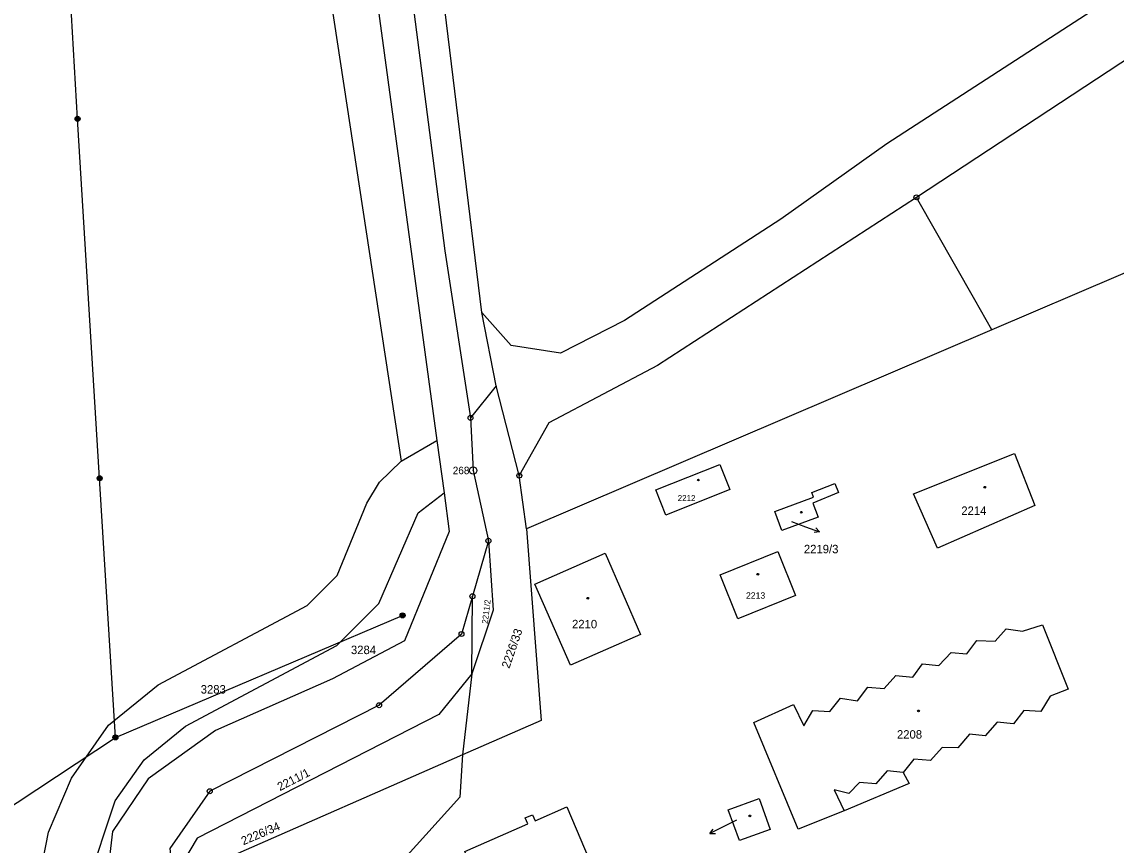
# Model space of a CAD drawing. Extents: x -504988 to -494607, y -1123820 to -1114018.
# Drawn here: x -498417.5 to -498197.3, y -1121313.5 to -1121148 of the extents above; entities that cross this region are included whole.
import ezdxf

# ---------------------------------------------------------------- set-up
doc = ezdxf.new("R2010")
doc.units = 0
for name, color, linetype in [('Hranice parcel', 7, 'Continuous'), ('Parcelní čísla', 7, 'Continuous'), ('Pop  PČ popisy', 7, 'Continuous'), ('Poz předměty', 7, 'Continuous'), ('Vnitřní kresba', 7, 'Continuous'), ('Značky bodu BP', 7, 'Continuous'), ('Značky budov', 7, 'Continuous')]:
    doc.layers.add(name, color=color, linetype=linetype)

msp = doc.modelspace()

# ---------------------------------------------------------------- linework, layer by layer
at = {"layer": 'Hranice parcel'}
for p, q in [((-498322.08, -1121221.18), (-498324.96, -1121206.38)), ((-498322.08, -1121221.18), (-498327.26, -1121227.59)), ((-498317.44, -1121239.21), (-498322.08, -1121221.18)), ((-498341.22, -1121236.34), (-498334.01, -1121232.13)), ((-498334.01, -1121232.13), (-498332.57, -1121242.67)), ((-498316.01, -1121249.89), (-498317.44, -1121239.21)), ((-498323.66, -1121252.32), (-498326.87, -1121263.48)), ((-498326.96, -1121279.11), (-498326.87, -1121263.48)), ((-498326.96, -1121279.11), (-498328.85, -1121295.4))]:
    msp.add_line(p, q, dxfattribs=at)
for points in [[(-498563.08, -1120498.99), (-498580.43, -1120580.76), (-498578.59, -1120613.62), (-498575.31, -1120622.92), (-498520.91, -1120731.15), (-498466.5, -1120839.37), (-498415.95, -1120939.68), (-498365.41, -1121039.98), (-498348, -1121129.42), (-498334.01, -1121232.13)], [(-498553.9, -1120501.92), (-498566.68, -1120548.32), (-498571.22, -1120567), (-498572.64, -1120575.69), (-498572.53, -1120600), (-498570.59, -1120612.91), (-498568.41, -1120619.25), (-498510.33, -1120737.36), (-498455.17, -1120846.3), (-498400, -1120955.23), (-498384.01, -1120988.03), (-498366.31, -1121020.42), (-498352.86, -1121051.29), (-498347.46, -1121078.01), (-498332.45, -1121193.98), (-498327.26, -1121227.59)], [(-497349.37, -1120589.26), (-497477.01, -1120672.48), (-497604.63, -1120755.71), (-497698.4, -1120816.44), (-497821.04, -1120898.04), (-497931.33, -1120969.32), (-498041.62, -1121040.59), (-498124.46, -1121095.39), (-498243.47, -1121172.51), (-498264.79, -1121187.65), (-498296.3, -1121208.05), (-498309.12, -1121214.61), (-498319.07, -1121213.07), (-498324.96, -1121206.38)], [(-498406.87, -1120973.99), (-498379.62, -1121026.82), (-498368.9, -1121054.8), (-498341.22, -1121236.34)], [(-498108.05, -1121098.26), (-498152.94, -1121127.65), (-498237.53, -1121183.25), (-498289.63, -1121217.05), (-498311.51, -1121228.58), (-498317.44, -1121239.21)], [(-498324.96, -1121206.38), (-498336.87, -1121109.08), (-498336.92, -1121099.93)], [(-498060.17, -1121236.77), (-498062.34, -1121231.06), (-498095.23, -1121155.58), (-498222.34, -1121209.87), (-498316.01, -1121249.89)], [(-498327.26, -1121227.59), (-498326.73, -1121238.18), (-498323.66, -1121252.32)], [(-498238.14, -1121242.9), (-498217.78, -1121234.79), (-498213.68, -1121245.25), (-498233.29, -1121253.81), (-498238.14, -1121242.9)], [(-498426.64, -1121336.91), (-498414.28, -1121321.57), (-498412.19, -1121310.9), (-498407.54, -1121300.06), (-498400.08, -1121289.41), (-498390.12, -1121281.33), (-498360.1, -1121265.36), (-498354.1, -1121259.32), (-498348.1, -1121244.76), (-498345.58, -1121240.51), (-498341.22, -1121236.34)], [(-498289.98, -1121242.1), (-498277.09, -1121236.95), (-498275.07, -1121242.02), (-498287.96, -1121247.17), (-498289.98, -1121242.1)], [(-498258.21, -1121243.54), (-498258.58, -1121242.61), (-498253.93, -1121240.78), (-498253.17, -1121242.64), (-498258.38, -1121244.73), (-498257.28, -1121247.59), (-498264.6, -1121250.24), (-498266.03, -1121246.41), (-498258.21, -1121243.54)], [(-498404.36, -1121321.42), (-498398.74, -1121304.65), (-498392.93, -1121296.36), (-498384.63, -1121289.63), (-498354.13, -1121273.4), (-498345.7, -1121264.91), (-498337.76, -1121246.73), (-498332.57, -1121242.67)], [(-498332.57, -1121242.67), (-498331.52, -1121250.43), (-498340.54, -1121272.48), (-498355.01, -1121280.09), (-498378.59, -1121290.5), (-498392.14, -1121300.21), (-498399.29, -1121310.78), (-498400.28, -1121319.41)], [(-498316.01, -1121249.89), (-498313.03, -1121288.47), (-498328.85, -1121295.4)], [(-498323.66, -1121252.32), (-498322.68, -1121266.26), (-498326.96, -1121279.11)], [(-498314.29, -1121261.02), (-498300.18, -1121254.84), (-498293.03, -1121271.15), (-498307.14, -1121277.33), (-498314.29, -1121261.02)], [(-498265.39, -1121254.5), (-498261.85, -1121263.33), (-498273.47, -1121268), (-498277.01, -1121259.17), (-498265.39, -1121254.5)], [(-498326.87, -1121263.48), (-498329.06, -1121271.08), (-498345.65, -1121285.4), (-498379.74, -1121302.69), (-498387.75, -1121314.21), (-498387.11, -1121320.27)], [(-498260.21, -1121289.52), (-498258.35, -1121286.43), (-498254.93, -1121286.63), (-498252.8, -1121283.95), (-498249.38, -1121284.5), (-498247.31, -1121281.76), (-498243.98, -1121282.06), (-498241.69, -1121279.44), (-498238.27, -1121279.74), (-498236.33, -1121277.06), (-498233, -1121277.39), (-498230.55, -1121274.8), (-498227.38, -1121275.07), (-498225.34, -1121272.39), (-498221.68, -1121272.53), (-498219.48, -1121270.03), (-498216.15, -1121270.49), (-498212.17, -1121269.21), (-498206.99, -1121282.15), (-498210.62, -1121283.58), (-498212.46, -1121286.69), (-498215.91, -1121286.49), (-498218.01, -1121289.14), (-498221.27, -1121288.83), (-498223.72, -1121291.58), (-498226.86, -1121291.22), (-498229.21, -1121293.97), (-498232.34, -1121293.91), (-498234.72, -1121296.5), (-498238.05, -1121296.27), (-498240.21, -1121298.92), (-498238.97, -1121301.17), (-498252.07, -1121306.67), (-498261.32, -1121310.36), (-498270.26, -1121288.9), (-498262.23, -1121285.26), (-498260.21, -1121289.52)], [(-498326.96, -1121279.11), (-498333.61, -1121287.28), (-498382.28, -1121312.11), (-498387.11, -1121320.27)], [(-498328.85, -1121295.4), (-498376.83, -1121316.44), (-498378.08, -1121339.71)], [(-498328.85, -1121295.4), (-498329.38, -1121303.91), (-498358.03, -1121335.63)], [(-498266.94, -1121310.38), (-498273.14, -1121312.63), (-498275.39, -1121306.43), (-498269.19, -1121304.18), (-498266.94, -1121310.38)], [(-498302.44, -1121318.61), (-498323.36, -1121327.36), (-498328.43, -1121314.82), (-498315.71, -1121309.26), (-498316.23, -1121308.07), (-498314.77, -1121307.43), (-498314.26, -1121308.62), (-498307.87, -1121305.83), (-498302.44, -1121318.61)]]:
    msp.add_lwpolyline(points, dxfattribs=at)
at = {"layer": 'Pop  PČ popisy'}
for p, q in [((-498262.66, -1121248.45), (-498259.84, -1121249.49)), ((-498259.84, -1121249.49), (-498257.02, -1121250.52)), ((-498257.02, -1121250.52), (-498258.13, -1121250.64)), ((-498257.02, -1121250.52), (-498257.79, -1121249.7)), ((-498276.42, -1121309.85), (-498279.09, -1121311.21)), ((-498273.75, -1121308.49), (-498276.42, -1121309.85)), ((-498279.09, -1121311.21), (-498278.43, -1121310.31)), ((-498279.09, -1121311.21), (-498277.97, -1121311.2))]:
    msp.add_line(p, q, dxfattribs=at)
at = {"layer": 'Poz předměty'}
for p, q in [((-498406.33, -1121167.45), (-498411.04, -1121088.43)), ((-498401.89, -1121239.75), (-498406.33, -1121167.45)), ((-498398.71, -1121291.87), (-498401.89, -1121239.75)), ((-498398.71, -1121291.87), (-498340.92, -1121267.33)), ((-498480.72, -1121346.17), (-498398.71, -1121291.87))]:
    msp.add_line(p, q, dxfattribs=at)
for centre, radius in [((-498406.33, -1121167.45), 0.5), ((-498406.33, -1121167.45), 0.4), ((-498406.33, -1121167.45), 0.3), ((-498406.33, -1121167.45), 0.2), ((-498406.33, -1121167.45), 0.1), ((-498401.89, -1121239.75), 0.5), ((-498401.89, -1121239.75), 0.4), ((-498401.89, -1121239.75), 0.3), ((-498401.89, -1121239.75), 0.2), ((-498401.89, -1121239.75), 0.1), ((-498340.92, -1121267.33), 0.5), ((-498340.92, -1121267.33), 0.4), ((-498340.92, -1121267.33), 0.3), ((-498340.92, -1121267.33), 0.2), ((-498340.92, -1121267.33), 0.1), ((-498398.71, -1121291.87), 0.5), ((-498398.71, -1121291.87), 0.4), ((-498398.71, -1121291.87), 0.3), ((-498398.71, -1121291.87), 0.2), ((-498398.71, -1121291.87), 0.1)]:
    msp.add_circle(centre, radius, dxfattribs=at)
at = {"layer": 'Vnitřní kresba'}
for p, q in [((-498225.78, -1121203.84), (-498237.53, -1121183.25)), ((-498222.34, -1121209.87), (-498225.78, -1121203.84)), ((-498243.41, -1121298.61), (-498245.67, -1121301.24)), ((-498240.21, -1121298.92), (-498243.41, -1121298.61)), ((-498248.97, -1121300.93), (-498251.14, -1121303.15)), ((-498245.67, -1121301.24), (-498248.97, -1121300.93)), ((-498251.14, -1121303.15), (-498254.08, -1121302.43)), ((-498254.08, -1121302.43), (-498252.07, -1121306.67))]:
    msp.add_line(p, q, dxfattribs=at)
at = {"layer": 'Značky bodu BP'}
for centre, radius in [((-498237.53, -1121183.25), 0.5), ((-498237.53, -1121183.25), 0.0303), ((-498327.26, -1121227.59), 0.5), ((-498327.26, -1121227.59), 0.0303), ((-498326.73, -1121238.18), 0.75), ((-498326.73, -1121238.18), 0.03), ((-498317.44, -1121239.21), 0.5), ((-498317.44, -1121239.21), 0.0303), ((-498323.66, -1121252.32), 0.5), ((-498323.66, -1121252.32), 0.0303), ((-498326.87, -1121263.48), 0.5), ((-498326.87, -1121263.48), 0.0303), ((-498329.06, -1121271.08), 0.5), ((-498329.06, -1121271.08), 0.0303), ((-498345.65, -1121285.4), 0.5), ((-498345.65, -1121285.4), 0.0303), ((-498379.74, -1121302.69), 0.5), ((-498379.74, -1121302.69), 0.0303)]:
    msp.add_circle(centre, radius, dxfattribs=at)
at = {"layer": 'Značky budov'}
for centre in [(-498281.4, -1121240.1), (-498223.77, -1121241.55), (-498260.69, -1121246.58), (-498269.44, -1121259.05), (-498303.67, -1121263.88), (-498237.1, -1121286.55), (-498271.05, -1121307.66)]:
    msp.add_circle(centre, 0.175, dxfattribs=at)

# ---------------------------------------------------------------- texts
at = {"layer": 'Parcelní čísla'}
for s, height, p in [('2212', 1.2, (-498285.56, -1121244.33)), ('2214', 1.7, (-498228.49, -1121247.12)), ('2219/3', 1.7, (-498260.17, -1121254.84)), ('2213', 1.3, (-498271.82, -1121263.98)), ('2210', 1.7, (-498306.83, -1121269.93)), ('3284', 1.7, (-498351.32, -1121275.12)), ('3283', 1.7, (-498381.55, -1121283.05)), ('2208', 1.7, (-498241.44, -1121292.12))]:
    msp.add_text(s, height=height, dxfattribs=at).set_placement(p)
for s, height, rotation, p in [('2211/2', 1.2, 83, (-498323.79, -1121269.09)), ('2226/33', 1.7, 71, (-498319.45, -1121278.12)), ('2211/1', 1.7, 27, (-498365.6, -1121302.68)), ('2226/34', 1.7, 23, (-498372.97, -1121313.58))]:
    msp.add_text(s, height=height, rotation=rotation, dxfattribs=at).set_placement(p)
at = {"layer": 'Značky bodu BP'}
msp.add_text('268', height=1.5, dxfattribs=at).set_placement((-498330.83, -1121238.93))

doc.saveas('drawing.dxf')
